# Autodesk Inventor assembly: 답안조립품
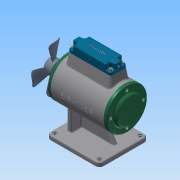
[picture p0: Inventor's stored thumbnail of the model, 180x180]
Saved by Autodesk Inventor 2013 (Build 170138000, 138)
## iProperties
Created: 2019-07
Part Number: 답안조립품
Document SubType Name: Assembly
Designer: Administrator
Mass: 3420.47 g
Surface Area: 2825.52 cm^2
Volume: 1021.3 cm^3
Density: 3.34915 g/cm^3
Author: Administrator
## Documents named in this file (19)
- C:\Users\Administrator\Desktop\390704V1005\답안조립품.iam
- C:\Users\Administrator\Desktop\390704V1005\본체.ipt
- C:\Users\Administrator\Desktop\390704V1005\15스프링.ipt
- C:\Users\Administrator\Desktop\390704V1005\16스프링.ipt
- C:\Users\Administrator\Desktop\390704V1005\17스프링.ipt
- C:\Users\Administrator\Desktop\390704V1005\뒤커버.ipt
- C:\Users\Administrator\Desktop\390704V1005\멈춤나사 M4 x 5.ipt
- C:\Users\Administrator\Desktop\390704V1005\베어링 6203.ipt
- C:\Users\Administrator\Desktop\390704V1005\볼트 M4 x 12.ipt
- C:\Users\Administrator\Desktop\390704V1005\볼트 M4 x 16.ipt
- C:\Users\Administrator\Desktop\390704V1005\부시.ipt
- C:\Users\Administrator\Desktop\390704V1005\슬라이드.ipt
- C:\Users\Administrator\Desktop\390704V1005\앞커버.ipt
- C:\Users\Administrator\Desktop\390704V1005\오일실 17 30 8.ipt
- C:\Users\Administrator\Desktop\390704V1005\축.ipt
- C:\Users\Administrator\Desktop\390704V1005\키 5 x 5 x 18.ipt
- C:\Users\Administrator\Desktop\390704V1005\팬날개.ipt
- 팬날개.ipt
- C:\Users\Administrator\Desktop\390704V1005\헤더커버.ipt
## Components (4 placed, 4 different names)
1. 15스프링:1
2. 16스프링:1
3. 17스프링:1
4. 헤더커버:1
